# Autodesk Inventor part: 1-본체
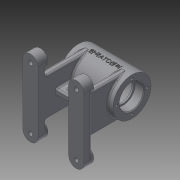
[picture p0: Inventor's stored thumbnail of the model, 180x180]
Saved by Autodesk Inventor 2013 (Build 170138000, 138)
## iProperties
Created: 2015-11
Part Number: 1-본체
Material: 일반
Document SubType Name: Modeling
Designer: Administrator
Density: 1 g/cm^3
Author: Administrator
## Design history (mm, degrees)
sketch "스케치1"
  geometry: L1 (-20, 40)-(-20, -40); L2 (-40, 40)-(-40, -40); L3 (0, 38.699)-(0, -51.087); A1 r 10 centre (-30, 40) between (-20, 40) and (-40, 40); A2 r 10 centre (-30, -40) between (-20, -40) and (-40, -40); 2 further points
  constraints: 6 end point, 4 point on circle, 4 tangent, 2 centre point, 1 horizontal alignment, 1 midpoint, 1 parallel, 1 point on line, 1 vertical, 1 vertical alignment
  dimensions: "d0" = 20 diameter of A1; "d2" = 80 distance of A2.centre A1.centre; "d3" = 80 diameter of L2 L3
extrude "돌출1" new body sketch "스케치1" distance "d4" = 10; taper "d5" = 0 deg
sketch "스케치2"
  geometry: C1 r 10 at (30, -40); C2 r 10 at (30, 40); A1 r 10 centre (30, -40) between (20, -40) and (40, -40) reference; A2 r 10 centre (30, 40) between (40, 40) and (20, 40) reference; 1 further point
  constraints: 2 centre point, 2 concentric
  dimensions: "d6" = 20 diameter of C1; "d8" = 20 diameter of C2
extrude "돌출2" join sketch "스케치2" distance "d9" = 3; taper "d10" = 0 deg
sketch "스케치3"
  geometry: L1 (20, -25)-(28, -25); L2 (28, -25)-(28, 25); L3 (28, 25)-(20, 25); L4 (20, 25)-(20, -25); L5 (20, 40)-(20, -40) reference; 2 further points
  constraints: 8 end point, 2 midpoint, 2 parallel, 1 horizontal, 1 perpendicular
  dimensions: "d11" = 50 distance of L3.end L1.start; "d13" = 8 distance of L1.start L1.end
extrude "돌출3" join sketch "스케치3" distance "d14" = 58; taper "d15" = 0 deg
fillet "모깎기1" dims "d16" = 2
sketch "스케치4"
  geometry: L1 (0, -40)-(0, 40) reference; C1 r 25 at (68, 0); 1 further point
  constraints: 1 centre point, 1 horizontal alignment
  dimensions: "d17" = 50 diameter of C1; "d19" = 68 distance from line of L1 C1.centre
extrude "돌출4" join sketch "스케치4" stored distance "d20" = 70; taper "d21" = 0 deg
sketch "스케치5"
  geometry: L1 (-20, 49.257)-(20, 49.257); L2 (20, 49.257)-(20, 23); L3 (20, 23)-(-20, 23); L4 (-20, 23)-(-20, 49.257); L5 (-35, 43)-(35, 43) reference; L6 (-20, 12)-(-20, 68) reference; L7 (20, 12)-(20, 68) reference; 1 further point
  constraints: 8 end point, 2 parallel, 2 point on line, 1 horizontal, 1 perpendicular
  dimensions: "d22" = 20 distance between parallel lines of L3 L5
extrude "돌출5" join sketch "스케치5" stored distance "d23" = 8; taper "d24" = 0 deg
sketch "스케치6"
  geometry: L1 (-46.712, 68)-(47.627, 68); L2 (-35, 93)-(-35, 43) reference; L3 (-35, 84)-(-23.3, 84); L4 (-23, 83.7)-(-23, 82); L5 (-23, 82)-(-21, 82); L6 (-21, 82)-(-21, 86); L7 (-18, 89)-(18, 89); L8 (21, 86)-(21, 82); L9 (21, 82)-(23, 82); L10 (23, 82)-(23, 83.7); L11 (23.3, 84)-(35, 84); L12 (35, 43)-(35, 93) reference; L13 (20, 43.322)-(-20, 43.322) reference; L14 (-35, 84)-(-35, 68); L15 (35, 84)-(35, 68); L16 (-35, 68)-(35, 68); A1 r 0.3 centre (-23.3, 83.7) between (-23, 83.7) and (-23.3, 84); A2 r 0.3 centre (23.3, 83.7) between (23.3, 84) and (23, 83.7); A3 r 3 centre (-18, 86) between (-18, 89) and (-21, 86); A4 r 3 centre (18, 86) between (21, 86) and (18, 89); 7 further points
  constraints: 26 end point, 11 point on line, 8 point on circle, 8 tangent, 5 parallel, 4 centre point, 4 midpoint, 3 collinear, 2 equal radius, 2 perpendicular, 1 horizontal, 1 vertical alignment
  dimensions: "d25" = 32 diameter of L3 L1; "d27" = 28 diameter of L5 L1; "d28" = 42 diameter of L7 L1; "d29" = 28 diameter of L9 L1; "d30" = 32 diameter of L11 L1; "d31" = 42 distance between parallel lines of L8 L6; "d32" = 12 distance between parallel lines of L2 L4; "d33" = 12 distance between parallel lines of L12 L10; "d35" = 0.3 radius of A1; "d36" = 3 radius of A3
revolve "회전1" sketch "스케치6" stored, may be unused: angle "d34" = 90 deg
chamfer "모따기1" distance "d37" = 1; stored, may be unused: second distance "d38" = 2, angle "d39" = 45 deg
sketch "스케치7"
  geometry: L1 (-8, 36.5)-(8, 36.5); L2 (8, 29.5)-(-8, 29.5); L3 (-20, 23)-(20, 23) reference; L4 (40, 0)-(20, 0) reference; A1 r 3.5 centre (-8, 33) between (-8, 36.5) and (-8, 29.5); A2 r 3.5 centre (8, 33) between (8, 36.5) and (8, 29.5); 5 further points
  constraints: 4 end point, 4 midpoint, 4 point on circle, 4 tangent, 2 centre point, 2 vertical alignment
  dimensions: "d40" = 7 diameter of A1; "d43" = 23 dimension on A2 A1; "d44" = 7 diameter of A2; "d45" = 33 distance from line of L4 A2.centre
extrude "돌출6" cut sketch "스케치7" distance "d46" = 8; taper "d47" = 0 deg
sketch "스케치8"
  geometry: L1 (0, 0)-(60, 0); L2 (60, 0)-(60, 80); L3 (60, 80)-(0, 80); L4 (0, 80)-(0, 0); C1 r 10 at (60, 0) reference; C2 r 10 at (0, 80) reference; 1 further point
  constraints: 8 end point, 2 coincident, 2 parallel, 1 horizontal, 1 perpendicular
  dimensions: "d67" = 60 distance of L1.start L1.end (derived); "d68" = 80 distance of L3.end L1.start (derived)
  node "투영된 루프1"
  node "투영된 루프2"
hole "구멍1" sketch "스케치8" diameter "d48" = 12; stored, may be unused: countersink angle "d52" = 90 deg, drill point angle "d54" = 0 deg; dims "d49" = 6, "d50" = 12, "d51" = 4, "d53" = 4
fillet "모깎기2" dims "d55" = 0.3
hole "구멍2" diameter "d58" = 6; stored, may be unused: countersink angle "d62" = 90 deg, drill point angle "d64" = 0 deg; dims "d59" = 6, "d60" = 8, "d61" = 4, "d63" = 20, "d65" = 10, "d66" = 10
fillet "모깎기3" dims "d75" = 2
sketch "스케치9"
  geometry: L1 (0, 0)-(0, 20); C1 r 25 at (0, 0) reference; C2 r 17 at (0, 0) reference; 1 further point
  constraints: 2 coincident, 2 end point, 1 vertical
  dimensions: "d77" = 20 distance of L1.start L1.end
hole "구멍3" sketch "스케치9" at (0, 20) diameter "d80" = 3.242; stored, may be unused: countersink angle "d84" = 90 deg, drill point angle "d86" = 118 deg; dims "d81" = 8, "d82" = 9, "d83" = 4, "d85" = 10
sketch "스케치10"
  geometry: L1 (0, 0)-(0, 20); C1 r 18 at (0, 0) reference; 1 further point
  constraints: 2 coincident, 2 end point, 1 vertical
  dimensions: "d90" = 20 distance of L1.start L1.end
hole "구멍4" sketch "스케치10" at (0, 20) diameter "d92" = 3.242; stored, may be unused: countersink angle "d96" = 90 deg, drill point angle "d98" = 118 deg; dims "d93" = 8, "d94" = 9, "d95" = 4, "d97" = 10
node "작업 평면3"
  node "작업 평면2"
sketch "스케치12"
  geometry: C1 r 5 at (0, 0); 1 further point
  constraints: 1 centre point, 1 coincident
  dimensions: "d104" = 10 diameter of C1
extrude "돌출7" join sketch "스케치12" distance "d106" = 4; taper "d107" = 0 deg
hole "구멍5" diameter "d110" = 5.188; stored, may be unused: countersink angle "d114" = 90 deg, drill point angle "d116" = 118 deg; dims "d108" = 10, "d109" = 10, "d111" = 15, "d112" = 9, "d113" = 4, "d115" = 20
sketch "스케치13"
  geometry: L1 (68, 0)-(43.751, -14); L2 (68, 0)-(44.303, 0); C1 r 17 at (68, 0) reference; 1 further point
  constraints: 4 end point, 1 horizontal
  dimensions: "d117" = 30 deg angle of L1 L2; "d118" = 28 distance of L1.start L1.end
node "작업 평면4"
sketch "스케치14"
  geometry: C1 r 6 at (0, 0); 1 further point
  constraints: 1 centre point
  dimensions: "d119" = 12 diameter of C1
extrude "돌출8" join sketch "스케치14" stored distance "d121" = 10; taper "d122" = 0 deg
hole "구멍6" diameter "d125" = 5.188; stored, may be unused: countersink angle "d129" = 90 deg, drill point angle "d131" = 118 deg; dims "d123" = 10, "d124" = 10, "d126" = 15, "d127" = 9, "d128" = 4, "d130" = 20
fillet "모깎기4" dims "d132" = 2
node "작업 평면5"
sketch "스케치15"
  geometry: L1 (-14.925, 2.384)-(14.925, 2.384); L2 (14.925, 2.384)-(14.925, -2.384); L3 (14.925, -2.384)-(-14.925, -2.384); L4 (-14.925, -2.384)-(-14.925, 2.384); L5 (-35, 25)-(-35, -25) reference; L6 (-35, 25)-(35, 25) reference; 5 further points
  constraints: 4 midpoint, 1 horizontal alignment, 1 vertical alignment, 2 other
feature "엠보싱1" sketch "스케치15" dims "d0" = 20, "d2" = 80, "d3" = 80, "d133" = 0.5, "d134" = 0
node "솔리드1"
mirror "대칭1"
pattern_linear "직사각형 패턴1"
pattern_circular "원형 패턴1" dims angle "d88" = 360 deg
pattern_circular "원형 패턴2" dims angle "d100" = 360 deg
node "투영된 루프3"
other parameters: "d103" = 3
